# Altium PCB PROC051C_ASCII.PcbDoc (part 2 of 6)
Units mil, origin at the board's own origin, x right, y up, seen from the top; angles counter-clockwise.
Board outline 3304.03 x 2647.77 mil, 6 copper layers (TOP, L2, L3, L4, L5, BOTTOM), stack 55.54 mil thick; 370 components, 273 nets, 1273 pads, 1381 vias.
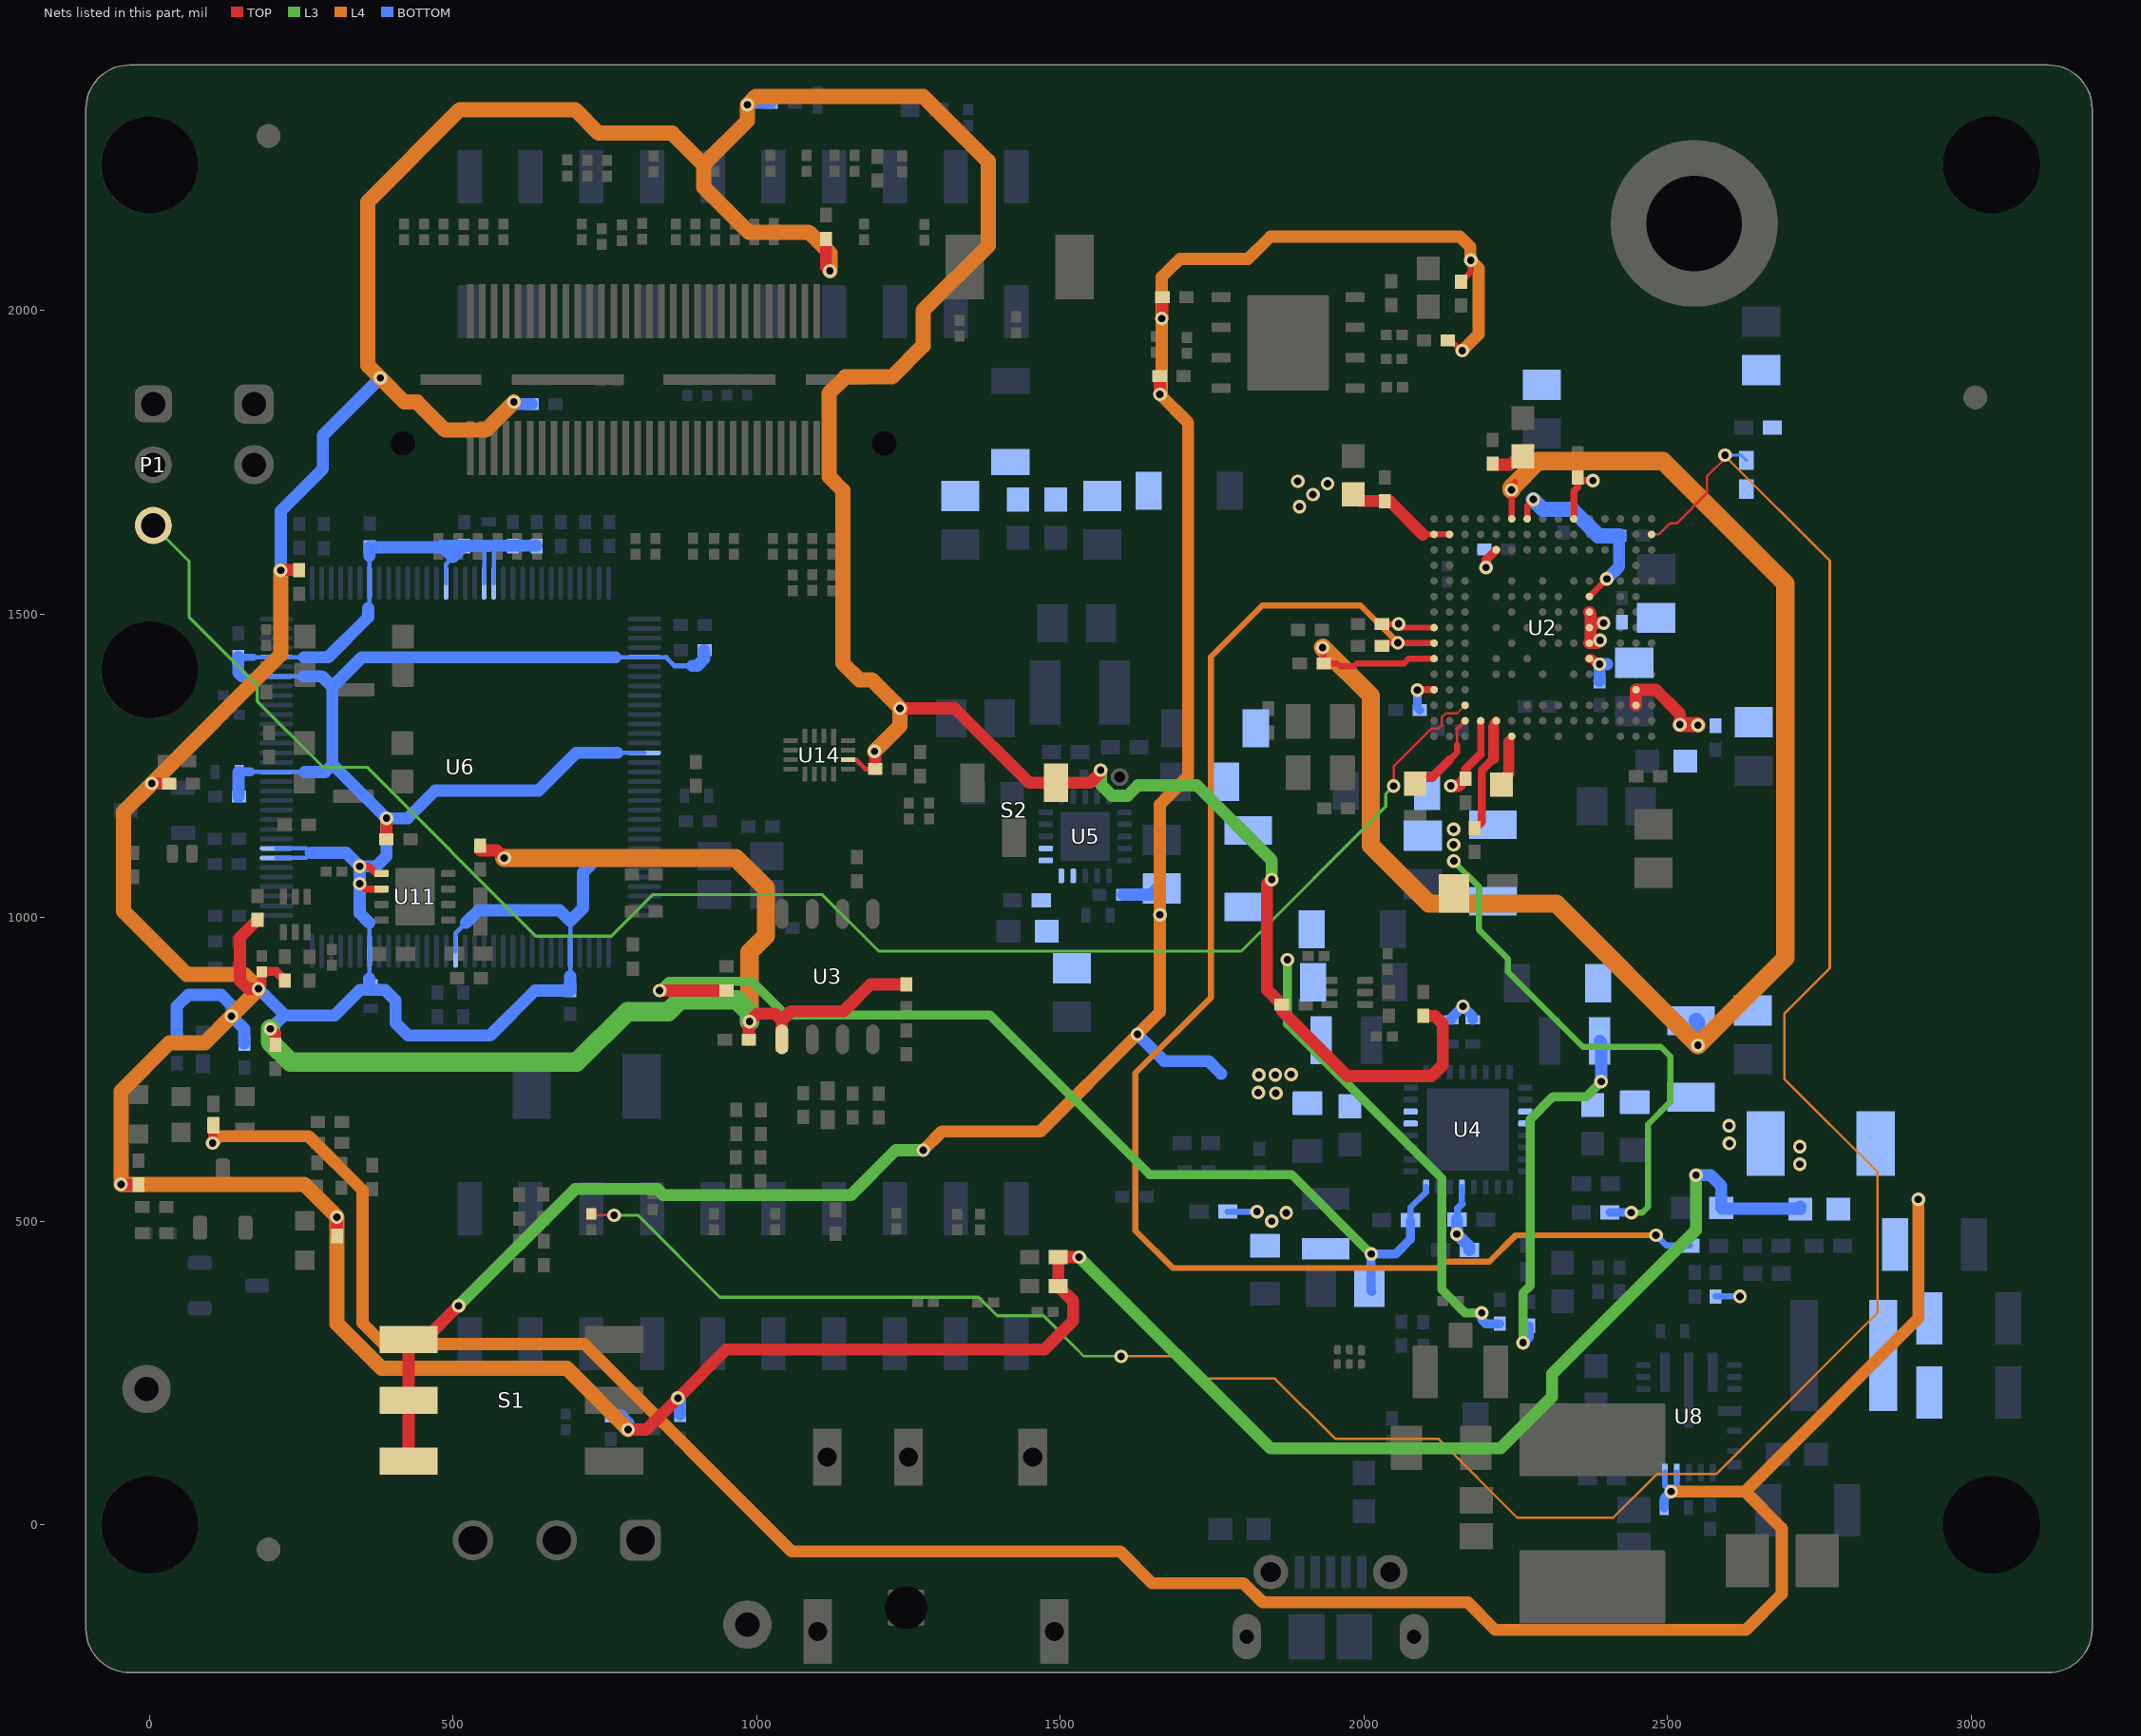
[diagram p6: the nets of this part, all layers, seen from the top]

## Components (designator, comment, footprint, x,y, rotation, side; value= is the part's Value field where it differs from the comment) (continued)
ZZ4 "These assemblies must comply with workmanship standards IPC-A-610 Class 2, unless otherwise specified." AssemblyNote -116.32,3327.82 r0 top
ZZ5 "Micro USB cable, Brackets, Screws, Nuts, Jumpers and Bump on need to be placed in a plastic bag" AssemblyNote -115.53,3255.05 r0 top

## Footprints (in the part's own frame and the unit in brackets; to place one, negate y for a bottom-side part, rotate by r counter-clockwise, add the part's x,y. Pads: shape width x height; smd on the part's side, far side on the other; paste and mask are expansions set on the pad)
0201 [mm] "Data from Kemet datasheet CC101_COM dated 7/28/11"
  rect 0.46x0.42 smd mask+0: 1(-0.33,0) 2(0.33,0)
0201_033 [mm] "SMD, 2-Leads, Height 0.33mm"
  rect 0.46x0.42 smd mask+0: 1(-0.33,0) 2(0.33,0)
0201_Silk [mm] "Data from Kemet datasheet CC101_COM dated 7/28/11"
  rect 0.46x0.42 smd mask+0: 1(-0.33,0) 2(0.33,0)
  silkscreen extent -0.75,-0.4 0.75,0.4
0402 [mm] "0402 from SM-752 data"
  rect 0.8x0.6 smd: 1(-0.6,0) 2(0.6,0)
  silkscreen extent -1.22,-0.52 1.22,0.52
0402_065L [mm] "0402"
  rect 0.6x0.5 smd: 1(-0.5,0) 2(0.5,0)
0402_070 [mil] "SMD, 2-Leads, Body 1.2x0.7mm, Height 0.7mm"
  rect 15x24 smd: 1(-20,0) 2(20,0)
0402L [mm] "0402 from SM-752 data"
  rect 0.6x0.5 smd: 1(-0.5,0) 2(0.5,0)
0402S [mil] "Based on C0402S footprint from PADS legacy"
  rect 15x24 smd: 1(-20,0) 2(20,0)
0603 [mm] "0603 from SM-752 data"
  rect 1x0.95 smd: 1(-0.8,0) 2(0.8,0)
  silkscreen extent -1.52,-0.69 1.52,0.69
0805_HV [mil] "0805 with 30mil clearance between pads"
  rect 50x63 smd: 1(-40,0) 2(40,0)
  silkscreen extent -74,-40 74,40
0805_HV1 [mm] "Custom footprint based on analyzing multiple manufacturer recommendations"
  rrect10% 1x1.25 smd: 1(-1,0) 2(1,0)
  silkscreen extent -0.2,-0.75 0.2,0.75
0805L [mm] "0805 from SM-752 data"
  rect 1.1x1.4 smd: 1(-0.75,0) 2(0.75,0)
1206 [mm] "1206 from SM-752 data"
  rect 1.3x1.85 smd: 1(-1.45,0) 2(1.45,0)
  silkscreen extent -2.4,-1.21 2.4,1.21
1206_180 [mm] "1206_180"
  rect 1.1x1.6 smd: 1(-1.7,0) 2(1.7,0)
  silkscreen extent -0.9,-1 0.9,1
1210_270 [mm] "1210"
  rect 1.3x2.7 smd: 1(-1.45,0) 2(1.45,0)
  silkscreen extent -2.32,-1.57 2.32,1.57
1210_280 [mm] "SMD, 2-Leads, Body 3.6x2.8mm, Height 2.8mm"
  rect 1.1x2.2 smd: 1(-1.65,0) 2(1.65,0)
  silkscreen extent -0.84,-1.4 0.84,1.4
2010 [mm] "Chip Capacitor, Body 5.08x2.54mm, IPC Medium Density"
  rect 1.6x2.7 smd: 1(-2.3,0) 2(2.3,0)
  silkscreen extent -3.42,-1.65 3.42,1.65
2220_345 [mm] "Wurth recommended land pattern"
  rrect3% 3.05x6.1 smd: 1(-3.075,0) 2(3.075,0)
  silkscreen extent -1.3,-3 1.3,3
3528-21 [mm] "Medium Density IPC, based on Kemet datasheet 2016-10-20"
  rrect6% 1.8x2.23 smd: 1(-1.46,0) 2(1.46,0)
  silkscreen extent -2.29,-1.5 0.76,1.5
ABL0161B [mm] "BGA, 161-Balls, Body 10.4x10.4mm, Pitch 0.65mm"
  round 0.32 smd: A1(-4.55,4.55) A2(-3.9,4.55) A3(-3.25,4.55) A5(-1.95,4.55) A7(-0.65,4.55) A9(0.65,4.55) A10(1.3,4.55) A13(3.25,4.55) A14(3.9,4.55) A15(4.55,4.55) B1(-4.55,3.9) B2(-3.9,3.9) B3(-3.25,3.9) B4(-2.6,3.9) B5(-1.95,3.9) B6(-1.3,3.9) B7(-0.65,3.9) B8(0,3.9) B9(0.65,3.9) B10(1.3,3.9) B11(1.95,3.9) B12(2.6,3.9) B13(3.25,3.9) B14(3.9,3.9) B15(4.55,3.9) C1(-4.55,3.25) C2(-3.9,3.25) C3(-3.25,3.25) C4(-2.6,3.25) C5(-1.95,3.25) C6(-1.3,3.25) C7(-0.65,3.25) C8(0,3.25) C9(0.65,3.25) C13(3.25,3.25) C14(3.9,3.25) C15(4.55,3.25) D2(-3.9,2.6) D13(3.25,2.6) D14(3.9,2.6) D15(4.55,2.6) E1(-4.55,1.95) E2(-3.9,1.95) E3(-3.25,1.95) E5(-1.95,1.95) E6(-1.3,1.95) E8(0,1.95) E10(1.3,1.95) E11(1.95,1.95) E13(3.25,1.95) E14(3.9,1.95) E15(4.55,1.95) F2(-3.9,1.3) F3(-3.25,1.3) F5(-1.95,1.3) F9(0.65,1.3) F11(1.95,1.3) F13(3.25,1.3) F14(3.9,1.3) F15(4.55,1.3) G1(-4.55,0.65) G2(-3.9,0.65) G3(-3.25,0.65) G5(-1.95,0.65) G6(-1.3,0.65) G7(-0.65,0.65) G8(0,0.65) G10(1.3,0.65) G13(3.25,0.65) G14(3.9,0.65) G15(4.55,0.65) H2(-3.9,0) H3(-3.25,0) H5(-1.95,0) H7(-0.65,0) H9(0.65,0) H11(1.95,0) H13(3.25,0) H14(3.9,0) H15(4.55,0) J1(-4.55,-0.65) J2(-3.9,-0.65) J3(-3.25,-0.65) J5(-1.95,-0.65) J6(-1.3,-0.65) J7(-0.65,-0.65) J8(0,-0.65) J10(1.3,-0.65) J13(3.25,-0.65) J14(3.9,-0.65) J15(4.55,-0.65) K2(-3.9,-1.3) K3(-3.25,-1.3) K5(-1.95,-1.3) K7(-0.65,-1.3) K8(0,-1.3) K9(0.65,-1.3) K10(1.3,-1.3) K11(1.95,-1.3) K13(3.25,-1.3) K14(3.9,-1.3) K15(4.55,-1.3) L1(-4.55,-1.95) L2(-3.9,-1.95) L3(-3.25,-1.95) L5(-1.95,-1.95) L6(-1.3,-1.95) L8(0,-1.95) L10(1.3,-1.95) L13(3.25,-1.95) L14(3.9,-1.95) L15(4.55,-1.95) M2(-3.9,-2.6) M3(-3.25,-2.6) M14(3.9,-2.6) M15(4.55,-2.6) N1(-4.55,-3.25) N2(-3.9,-3.25) N3(-3.25,-3.25) N4(-2.6,-3.25) N5(-1.95,-3.25) N6(-1.3,-3.25) N7(-0.65,-3.25) N8(0,-3.25) N9(0.65,-3.25) N10(1.3,-3.25) N11(1.95,-3.25) N12(2.6,-3.25) N13(3.25,-3.25) N14(3.9,-3.25) N15(4.55,-3.25) P1(-4.55,-3.9) P2(-3.9,-3.9) P3(-3.25,-3.9) P4(-2.6,-3.9) P5(-1.95,-3.9) P6(-1.3,-3.9) P7(-0.65,-3.9) P8(0,-3.9) P9(0.65,-3.9) P10(1.3,-3.9) P11(1.95,-3.9) P12(2.6,-3.9) P13(3.25,-3.9) P14(3.9,-3.9) P15(4.55,-3.9) R1(-4.55,-4.55) R2(-3.9,-4.55) R3(-3.25,-4.55) R4(-2.6,-4.55) R5(-1.95,-4.55) R6(-1.3,-4.55) R7(-0.65,-4.55) R8(0,-4.55) R9(0.65,-4.55) R10(1.3,-4.55) R11(1.95,-4.55) R12(2.6,-4.55) R13(3.25,-4.55) R14(3.9,-4.55) R15(4.55,-4.55)
  silkscreen extent -5.3,-5.3 5.3,5.3
APHHS1005_Green [mm] "SMD, 2-Leads, Body 1x0.5mm"
  rrect20% 0.7x0.5 smd: 1(-0.45,0) 2(0.45,0)
  silkscreen extent -0.8,-0.65 1.2,0.65
AssemblyNote [mil] "Assembly Note"
AssemblyNoteLabel [mil] "Assembly Note for PCB Labels"
CE_Mark_5mm [mil] "Minimum text height for CE Mark"
CONN_105017-0001 [mm] "Molex Micro USB-B"
  rect 0.4x1.35 smd: 1(-1.3,1.35) 2(-0.65,1.35) 3(0,1.35) 4(0.65,1.35) 5(1.3,1.35)
  oval 1.2x1.9 hole 0.6 slot 1.3 at 90 deg: 6(-3.5,-1.35) 9(3.5,-1.35)
  rect 1.5x1.9 smd: 7(-1,-1.35) 8(1,-1.35)
  round 1.45 hole 0.85: 10(2.5,1.35) 11(-2.5,1.35)
  TOP region: -3.5,-0.4 -2.3,-0.4 -2.3,-2.3 -3.5,-2.3
  TOP region: 3.5,-2.3 2.3,-2.3 2.3,-0.4 3.5,-0.4
  silkscreen extent -4.1,-0.2 4.1,1.4
CUI_PJ-051AH [mm] "DC Power Jack, R/A, TH"
  rrect8% 2.4x1.2 hole 0.8 square: 1(-6.3,3.3) 2(-6.3,-5.3) 3(-6.3,-0.1)
  rrect8% 2.7x1.2 hole 0.8 square: 4(1,-6.2) 5(1,3.7)
  rrect7% 1.5x1.5 hole 1.8 square unplated mask+0: MH1(0,0)
D0008A_L [mm] "SOIC, 8-Leads, Body 4.9x3.9mm, Pitch 1.27mm, IPC High Density"
  oval 1.25x0.55 smd: 1(-2.625,1.905) 2(-2.625,0.635) 3(-2.625,-0.635) 4(-2.625,-1.905) 5(2.625,-1.905) 6(2.625,-0.635) 7(2.625,0.635) 8(2.625,1.905)
  silkscreen extent -3.1,-2.5 0.9,2.5
DBZ0003A_N [mm] "SOT23, 3-Leads, Body 2.9x1.3mm, Pitch 0.95mm, Lead Span 2.4mm, IPC Medium Density"
  rrect17% 1x0.6 smd: 1(-1.2,0.95) 2(-1.2,-0.95) 3(1.2,0)
  silkscreen extent 0.2,-1.5 0.7,1.5
DFE252012P [mm] "TOKO, Pad sizes increased as per request"
  rect 0.9x2 smd: 1(-1.05,0) 2(1.05,0)
  silkscreen extent -0.3,-1.2 0.3,1.2
DRB0008B [mm] "SON, 8-Leads, Body 3x3mm, Pitch 0.65mm, Thermal Pad 2.4x1.65mm, TI Recommended"
  rrect33% 0.6x0.3 smd: 1(-1.4,0.975) 2(-1.4,0.325) 3(-1.4,-0.325) 4(-1.4,-0.975) 5(1.4,-0.975) 6(1.4,-0.325) 7(1.4,0.325) 8(1.4,0.975)
  rrect9% 1.47x1.06 on Top Paste: 9(0,-0.63) 9(0,0.63)
  rrect6% 1.65x2.4 smd paste-1.2: 9(0,0)
  silkscreen extent -1.73,-1.73 1.73,1.73
DRL0006A [mm] "SOTFL, 6-Flat Leads, Body 1.2x1.6x0.6mm, Pitch 0.5mm, TI recommended"
  rrect33% 0.67x0.3 smd: 1(-0.74,0.5) 2(-0.74,0) 3(-0.74,-0.5) 4(0.74,-0.5) 5(0.74,0) 6(0.74,0.5)
  silkscreen extent -0.9,-0.95 0.5,0.95
DRY0006A [mm] "USON-6"
  rrect67% 0.45x0.3 smd paste-0.05 mask+0: 1(-0.275,0.5)
  rrect67% 0.4x0.3 smd paste-0.05 mask+0: 2(-0.3,0) 3(-0.3,-0.5) 4(0.3,-0.5) 5(0.3,0) 6(0.3,0.5)
ESD_Overlay_Small [mil]
  silkscreen extent -62,-48 64,61
FCC_disclaimer [mil]
FIDUCIAL10-20 [mm]
  round 1 smd mask+0: 1(0,0)
  TOP keep-out circle w1.178: c0,0 r0.5
IEC_HotSurface_Small [mil]
  silkscreen extent -107,-93 107,92
JOHNSON_128-0711-201 [mm] "UMC Straight Jack Receptacle, 50 Ohm, SMT"
  rrect10% 1x1.05 smd: 1(0,1.525)
  rrect10% 1.05x2.2 smd: 2(-1.475,0) 3(1.475,0)
  silkscreen extent -0.6,-1.3 0.6,-1.3
Keystone5001 [mil] "For Keystone 500x miniature loop terminals"
  round 80 hole 40: 1(0,0)
  silkscreen extent -52,-52 52,52
KYOCERA_CX3225SA [mm] "SMD, 4-Leads, Body 3.2x2.5mm"
  rrect10% 1.05x1.45 smd: 1(-0.925,1.075) 2(-0.925,-1.075) 3(0.925,-1.075) 4(0.925,1.075)
  silkscreen extent -1.78,1.63 -1.65,1.76
Label_650x200 [mil] "Thermal Transfer Label"
  round 1 on Mech13: 0(0,0)
  silkscreen extent -325,-100 325,100
"LS L29K_Red" [mm] "SMD, 2-Leads, Body 1.3x0.8mm"
  rect 0.8x0.8 smd paste-0.4: 1(-0.75,0) 2(0.75,0)
  silkscreen extent -0.1,-0.5 1.45,0.5
NDK_NX3225SA [mm] "NDK"
  rect 1.2x1.4 smd: 1(-0.8,1.1) 2(-0.8,-1.1) 3(0.8,-1.1) 4(0.8,1.1)
NLCV32 [mm] "TDK"
  rect 1.2x2 smd: 1(-1.6,0) 2(1.6,0)
  silkscreen extent -0.9,-1.4 0.9,1.4
ON-SHORE_OSTTE030161 [mm] "Terminal Block, 3.5mm, 3x1, TH"
  rrect50% 1.7x1.7 hole 1.2: 1(-3.5,0)
  round 1.7 hole 1.2: 2(0,0) 3(3.5,0)
  silkscreen extent -5.25,-3.6 5.25,4.05
PDT0128A [mm] "Thin QFP, 128-Leads, Body 14x14mm, Pitch 0.4mm"
  oval 1.4x0.2 smd: 1(-7.7,6.2) 2(-7.7,5.8) 3(-7.7,5.4) 4(-7.7,5) 5(-7.7,4.6) 6(-7.7,4.2) 7(-7.7,3.8) 8(-7.7,3.4) 9(-7.7,3) 10(-7.7,2.6) 11(-7.7,2.2) 12(-7.7,1.8) 13(-7.7,1.4) 14(-7.7,1) 15(-7.7,0.6) 16(-7.7,0.2) 17(-7.7,-0.2) 18(-7.7,-0.6) 19(-7.7,-1) 20(-7.7,-1.4) 21(-7.7,-1.8) 22(-7.7,-2.2) 23(-7.7,-2.6) 24(-7.7,-3) 25(-7.7,-3.4) 26(-7.7,-3.8) 27(-7.7,-4.2) 28(-7.7,-4.6) 29(-7.7,-5) 30(-7.7,-5.4) 31(-7.7,-5.8) 32(-7.7,-6.2) 65(7.7,-6.2) 66(7.7,-5.8) 67(7.7,-5.4) 68(7.7,-5) 69(7.7,-4.6) 70(7.7,-4.2) 71(7.7,-3.8) 72(7.7,-3.4) 73(7.7,-3) 74(7.7,-2.6) 75(7.7,-2.2) 76(7.7,-1.8) 77(7.7,-1.4) 78(7.7,-1) 79(7.7,-0.6) 80(7.7,-0.2) 81(7.7,0.2) 82(7.7,0.6) 83(7.7,1) 84(7.7,1.4) 85(7.7,1.8) 86(7.7,2.2) 87(7.7,2.6) 88(7.7,3) 89(7.7,3.4) 90(7.7,3.8) 91(7.7,4.2) 92(7.7,4.6) 93(7.7,5) 94(7.7,5.4) 95(7.7,5.8) 96(7.7,6.2)
  oval 0.2x1.4 smd: 33(-6.2,-7.7) 34(-5.8,-7.7) 35(-5.4,-7.7) 36(-5,-7.7) 37(-4.6,-7.7) 38(-4.2,-7.7) 39(-3.8,-7.7) 40(-3.4,-7.7) 41(-3,-7.7) 42(-2.6,-7.7) 43(-2.2,-7.7) 44(-1.8,-7.7) 45(-1.4,-7.7) 46(-1,-7.7) 47(-0.6,-7.7) 48(-0.2,-7.7) 49(0.2,-7.7) 50(0.6,-7.7) 51(1,-7.7) 52(1.4,-7.7) 53(1.8,-7.7) 54(2.2,-7.7) 55(2.6,-7.7) 56(3,-7.7) 57(3.4,-7.7) 58(3.8,-7.7) 59(4.2,-7.7) 60(4.6,-7.7) 61(5,-7.7) 62(5.4,-7.7) 63(5.8,-7.7) 64(6.2,-7.7) 97(6.2,7.7) 98(5.8,7.7) 99(5.4,7.7) 100(5,7.7) 101(4.6,7.7) 102(4.2,7.7) 103(3.8,7.7) 104(3.4,7.7) 105(3,7.7) 106(2.6,7.7) 107(2.2,7.7) 108(1.8,7.7) 109(1.4,7.7) 110(1,7.7) 111(0.6,7.7) 112(0.2,7.7) 113(-0.2,7.7) 114(-0.6,7.7) 115(-1,7.7) 116(-1.4,7.7) 117(-1.8,7.7) 118(-2.2,7.7) 119(-2.6,7.7) 120(-3,7.7) 121(-3.4,7.7) 122(-3.8,7.7) 123(-4.2,7.7) 124(-4.6,7.7) 125(-5,7.7) 126(-5.4,7.7) 127(-5.8,7.7) 128(-6.2,7.7)
  silkscreen extent -7.7,-6.3 6.3,6.99
RGR0020A [mm] "QFN, 20-Leads, Body 3.5x3.5mm, Pitch 0.5mm, Thermal Pad 2.05x2.05mm, TI Recommended"
  rrect42% 0.6x0.24 smd: 1(-1.65,1) 2(-1.65,0.5) 3(-1.65,0) 4(-1.65,-0.5) 5(-1.65,-1) 11(1.65,-1) 12(1.65,-0.5) 13(1.65,0) 14(1.65,0.5) 15(1.65,1)
  rrect42% 0.24x0.6 smd: 6(-1,-1.65) 7(-0.5,-1.65) 8(0,-1.65) 9(0.5,-1.65) 10(1,-1.65) 16(1,1.65) 17(0.5,1.65) 18(0,1.65) 19(-0.5,1.65) 20(-1,1.65)
  rrect5% 2.05x2.05 smd paste-1.025: 21(0,0)
  silkscreen extent -1.97,-1.97 1.97,1.97
RHB0032N [mm] "QFN, 32-Leads, Body 5x5mm, Pitch 0.5mm, Thermal Pad 3.45x3.45mm"
  rrect40% 0.6x0.25 smd: 1(-2.4,1.75) 2(-2.4,1.25) 3(-2.4,0.75) 4(-2.4,0.25) 5(-2.4,-0.25) 6(-2.4,-0.75) 7(-2.4,-1.25) 8(-2.4,-1.75) 17(2.4,-1.75) 18(2.4,-1.25) 19(2.4,-0.75) 20(2.4,-0.25) 21(2.4,0.25) 22(2.4,0.75) 23(2.4,1.25) 24(2.4,1.75)
  rrect40% 0.25x0.6 smd: 9(-1.75,-2.4) 10(-1.25,-2.4) 11(-0.75,-2.4) 12(-0.25,-2.4) 13(0.25,-2.4) 14(0.75,-2.4) 15(1.25,-2.4) 16(1.75,-2.4) 25(1.75,2.4) 26(1.25,2.4) 27(0.75,2.4) 28(0.25,2.4) 29(-0.25,2.4) 30(-0.75,2.4) 31(-1.25,2.4) 32(-1.75,2.4)
  rrect3% 3.45x3.45 smd paste-1.725: 33(0,0)
  rrect7% 1.49x1.49 on Bottom Paste: ""(-0.845,-0.845) ""(-0.845,0.845) ""(0.845,-0.845) ""(0.845,0.845)
  silkscreen extent -2.72,-2.73 2.72,2.73
RNL0022A_NV [mm] "VQFN-HR-22"
  rrect25% 0.6x0.4 smd: 1(-1.9,2) 17(1.9,2)
  rrect40% 0.6x0.25 smd: 2(-1.9,1.425) 3(-1.9,0.575) 5(-1.9,-1.175) 6(-1.9,-1.675) 7(-1.9,-2.175) 11(1.9,-2.175) 12(1.9,-1.675) 13(1.9,-1.175) 15(1.9,0.575) 16(1.9,1.425)
  rrect25% 1x0.4 smd paste-0.25: 4(-1.7,-0.25) 14(1.7,-0.25)
  rrect25% 0.4x0.4 on Bottom Paste: 4A(-2,-0.25) 4B(-1.4,-0.25) 14A(1.4,-0.25) 14B(2,-0.25)
  rrect25% 0.4x1.65 smd paste-0.25: 8(-1,-1.875) 10(1,-1.875)
  rrect25% 0.4x0.66 on Bottom Paste: 8A(-1,-1.445) 8B(-1,-2.305) 10A(1,-1.445) 10B(1,-2.305)
  rrect25% 0.4x3.15 smd paste-0.25: 9(0,-1.125)
  rrect25% 0.4x0.63 on Bottom Paste: 9A(0,0.12) 9B(0,-0.71) 9C(0,-1.54) 9D(0,-2.37)
  rrect40% 0.25x0.75 smd: 18(1,2.325) 19(0.5,2.325) 20(0,2.325) 21(-0.5,2.325) 22(-1,2.325)
RSV0016A [mm] "QFN, 16-Leads, Body 1.8x2.6mm, Pitch 0.4mm, TI Recommended"
  rect 0.7x0.2 smd: 1(-0.75,0.6)
  rect 0.6x0.2 smd: 2(-0.8,0.2) 3(-0.8,-0.2) 4(-0.8,-0.6) 9(0.8,-0.6) 10(0.8,-0.2) 11(0.8,0.2) 12(0.8,0.6)
  rect 0.2x0.6 smd: 5(-0.6,-1.2) 6(-0.2,-1.2) 7(0.2,-1.2) 8(0.6,-1.2) 13(0.6,1.2) 14(0.2,1.2) 15(-0.2,1.2) 16(-0.6,1.2)
  silkscreen extent -1.08,-1.33 1.08,1.45
SAMTEC_QSH-030-01-X-D-A [mm] "Receptacle, 0.5 mm, 30x2, TH"
  rect 2.27x0.279 smd: 1(-2.865,7.25) 2(2.865,7.25) 3(-2.865,6.75) 4(2.865,6.75) 5(-2.865,6.25) 6(2.865,6.25) 7(-2.865,5.75) 8(2.865,5.75) 9(-2.865,5.25) 10(2.865,5.25) 11(-2.865,4.75) 12(2.865,4.75) 13(-2.865,4.25) 14(2.865,4.25) 15(-2.865,3.75) 16(2.865,3.75) 17(-2.865,3.25) 18(2.865,3.25) 19(-2.865,2.75) 20(2.865,2.75) 21(-2.865,2.25) 22(2.865,2.25) 23(-2.865,1.75) 24(2.865,1.75) 25(-2.865,1.25) 26(2.865,1.25) 27(-2.865,0.75) 28(2.865,0.75) 29(-2.865,0.25) 30(2.865,0.25) 31(-2.865,-0.25) 32(2.865,-0.25) 33(-2.865,-0.75) 34(2.865,-0.75) 35(-2.865,-1.25) 36(2.865,-1.25) 37(-2.865,-1.75) 38(2.865,-1.75) 39(-2.865,-2.25) 40(2.865,-2.25) 41(-2.865,-2.75) 42(2.865,-2.75) 43(-2.865,-3.25) 44(2.865,-3.25) 45(-2.865,-3.75) 46(2.865,-3.75) 47(-2.865,-4.25) 48(2.865,-4.25) 49(-2.865,-4.75) 50(2.865,-4.75) 51(-2.865,-5.25) 52(2.865,-5.25) 53(-2.865,-5.75) 54(2.865,-5.75) 55(-2.865,-6.25) 56(2.865,-6.25) 57(-2.865,-6.75) 58(2.865,-6.75) 59(-2.865,-7.25) 60(2.865,-7.25)
  round 0 hole 1.02 unplated mask+0: MH1(2.67,10.065) MH2(2.67,-10.065)
  rect 0.43x2.54 smd: MP1(0,8.065) MP4(0,-8.065)
  rect 0.43x4.7 smd: MP2(0,3.175) MP3(0,-3.175)
  silkscreen extent -3.9,-10.66 3.62,10.66
SAMTEC_SSM-110-X-DV [mm] "Receptacle, 2.54mm, 10x2, SMT"
  rrect10% 1.02x2.22 smd: 1(-11.43,2.825) 2(-11.43,-2.825) 3(-8.89,2.825) 4(-8.89,-2.825) 5(-6.35,2.825) 6(-6.35,-2.825) 7(-3.81,2.825) 8(-3.81,-2.825) 9(-1.27,2.825) 10(-1.27,-2.825) 11(1.27,2.825) 12(1.27,-2.825) 13(3.81,2.825) 14(3.81,-2.825) 15(6.35,2.825) 16(6.35,-2.825) 17(8.89,2.825) 18(8.89,-2.825) 19(11.43,2.825) 20(11.43,-2.825)
  silkscreen extent -13.02,-2.54 12.7,2.54
Samtec_TSW-103-07-T-S [mm] "Header, 2.54 mm, 3x1, TH"
  rrect50% 1.55x1.55 hole 1.02: 1(-2.54,0)
  round 1.55 hole 1.02: 2(0,0) 3(2.54,0)
SML-E1_Yellow [mm] "SMD, 2-Leads, Body 1.6x0.8mm"
  rect 0.8x0.8 smd: 1(0.825,0) 2(-0.825,0)
  silkscreen extent -1.8,-0.8 1.3,0.8
SOD-882 [mm] "Skyworks"
  rrect42% 0.475x0.75 smd mask+0: 1(-0.412,0) 2(0.412,0)
  rrect42% 0.475x0.75 on Top Solder mask+0: 1(-0.412,0) 2(0.412,0)
  silkscreen extent -1.1,-0.35 -0.87,0.35
SOT-23 [mm] "SOT23, 3-Leads, Body 2.9x1.3mm, Pitch 0.95mm, Lead Span 2.5mm, IPC Medium Density"
  rrect50% 1x0.6 smd: 1(-1.2,0.95) 2(-1.2,-0.95) 3(1.2,0)
  silkscreen extent -1.62,-1.5 0.7,1.5
SW_219-3MST [mm] "SMD, 6-Leads, Body 6.7x9.09mm, Pitch 2.54mm"
  rect 2.44x1.13 smd: 1(-4.3,2.54) 2(-4.3,0) 3(-4.3,-2.54) 4(4.3,-2.54) 5(4.3,0) 6(4.3,2.54)
  silkscreen extent -3.35,-4.54 3.35,4.54
SW_CJS_1201A [mm] "Copal- Electronics"
  rect 1x1.6 smd paste+0 mask+0: 1(-1.75,-1.15) 2(0,1.15) 3(1.75,-1.15)
  silkscreen extent -3,-1.6 -2.7,-0.8
SW_KMR243GLFG [mm] "SMD, 5-Leads, Body 4.2x2.8mm"
  rrect11% 0.9x1 smd: 1(-2.05,0.8) 2(2.05,0.8) 3(-2.05,-0.8) 4(2.05,-0.8)
  rrect18% 1.7x0.55 smd: 5(0,1.425)
  silkscreen extent -3.1,0.7 -2.9,0.9
TI_STACKED_OVERLAY_SMALL [mil]
TP_H045P075 [mm] "TP_H0.45P0.75"
  round 0.75 hole 0.45: 1(0,0)
TSW-102-07-G-S [mm] "Samtec 100mil, 1x2, 230 mil above insulator"
  rrect50% 1.65x1.65 hole 1.016: 1(-1.27,0)
  round 1.65 hole 1.016: 2(1.27,0)
WEEE_Minimum [mil] "WEEElie bin"
  silkscreen extent 22,-71 54,74
WSON-8L_6x5MM_EP [mm] "SMD, 8-Leads, Body 6x5mm, Pitch 1.27mm"
  rrect25% 0.8x0.4 smd: 1(-2.8,1.905) 2(-2.8,0.635) 3(-2.8,-0.635) 4(-2.8,-1.905) 5(2.8,-1.905) 6(2.8,-0.635) 7(2.8,0.635) 8(2.8,1.905)
  rrect3% 3.4x4 smd paste-3: 9(0,0)
  rrect7% 1.468x1.698 on Top Paste: ""(-0.834,-0.949) ""(-0.834,0.949) ""(0.834,-0.949) ""(0.834,0.949)
  silkscreen extent -3.2,-2.7 3.2,2.7
XAL5030 [mil] "Coilcraft XAL5030 12/12/11"
  rect 46x183 smd: 1(-65,0) 2(65,0)
  silkscreen extent -108,-112 108,112

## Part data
C1 C13 C14 C33 C36 C54 C94: library part CMP-0007136-5, "CAP, CERM, 1 uF, 16 V, +/- 10%, X7R, AEC-Q200 Grade 1, 0603"
C2: library part CMP-0006325-2, "CAP, CERM, 0.1 uF, 50 V, +/- 10%, X7R, AEC-Q200 Grade 1, 0402"
C3 C5 C7 C10 C12 C39 C47 C48 C51 C53 C56 C57 C84 C90: library part CMP-0078265-1, "CAP, CERM, 0.22 µF, 16 V,+/- 10%, X7R, AEC-Q200 Grade 1, 0402"
C4 C6 C11 C22: library part CMP-0006351-2, "CAP, CERM, 0.1 uF, 16 V, +/- 10%, X7R, 0402"
C8: library part CMP-0064969-1, "CAP, CERM, 0.1 uF, 10 V,+/- 10%, X7S, 0201"
C9 C15: library part CMP-0006367-2, "CAP, CERM, 4.7 pF, 50 V, +/- 2%, C0G/NP0, 0402"
C16 C20 C42 C43 C49 C64 C67 C71 C75 C91 C92 C97: library part CMP-0078241-1, "CAP, CERM, 0.1 µF, 10 V,+/- 10%, X7R, 0402"
C17 C40 C45 C52 C55 C58 C59 C65 C80 C83 C95 C96 C98 C100 C102 C103 C104: library part CMP-0008017-2, "CAP, CERM, 10 uF, 10 V, +/- 10%, X7R, 0805"
C18: library part CMP-0006717-2, "CAP, CERM, 0.47 uF, 6.3 V, +/- 10%, X7R, 0402"
C19 C37 C99 C105: library part CMP-0008770-2, "CAP, CERM, 22 uF, 6.3 V, +/- 10%, X7R, AEC-Q200 Grade 1, 1206"
C21 C25: library part CMP-0009155-2, "CAP, CERM, 10 uF, 25 V, +/- 20%, X7R, AEC-Q200 Grade 1, 1210"
C23 C27: library part CMP-0085252-1, "CAP, CERM, 0.047 µF, 50 V,+/- 5%, X7R, 0603"
C24: library part CMP-0006361-2, "CAP, CERM, 4700 pF, 50 V, +/- 10%, X7R, AEC-Q200 Grade 1, 0402"
C26: library part CMP-0078216-1, "CAP, TA, 47 µF, 10 V, +/- 10%, SMD"
C28 C34 C77 C78 C82: library part CMP-0006201-2, "CAP, CERM, 0.1 uF, 16 V, +/- 10%, X7R, 0402"
C29 C30 C31: library part CMP-0009174-2, "CAP, CERM, 22 uF, 16 V, +/- 10%, X7R, 1210"
C32 C79: library part CMP-0076706-1, "CAP, CERM, 4.7 µF, 25 V,+/- 10%, X7R, AEC-Q200 Grade 1, 0805"
C35 C46 C81: library part CMP-0007995-2, "CAP, CERM, 10 uF, 16 V, +/- 10%, X7R, 0805"
C38 C60 C68: library part CMP-0008809-2, "CAP, CERM, 22 uF, 6.3 V, +/- 10%, X7R, AEC-Q200 Grade 1, 1206"
C41 C61 C62 C76: library part CMP-0006349-2, "CAP, CERM, 1 uF, 10 V, +/- 10%, X7S, AEC-Q200 Grade 1, 0402"
C44: library part CMP-0009172-2, "CAP, CERM, 47 uF, 6.3 V, +/- 10%, X7R, AEC-Q200 Grade 1, 1210"
C50 C66 C69: library part CMP-0078218-1, "CAP, CERM, 0.01 µF, 16 V,+/- 10%, X7R, 0402"
C63 C70: library part CMP-0087060-3, "Cap Ceramic 8pF 50V C0G 0.5pF SMD 0402 125C Paper T/R"
C72 C73 C101: library part CMP-0006352-2, "CAP, CERM, 0.01 uF, 25 V, +/- 10%, X7R, 0402"
C74 C86: library part CMP-0006302-2, "CAP, CERM, 2.2 uF, 10 V, +/- 10%, X7S, 0402"
C85: library part CMP-0006624-2, "CAP, CERM, 1 uF, 6.3 V, +/- 20%, X7R, 0402"
C87 C89: library part CMP-0007134-5, "CAP, CERM, 2.2 uF, 6.3 V, +/- 10%, X7R, AEC-Q200 Grade 1, 0603"
C88: library part CMP-0006242-2, "CAP, CERM, 33 pF, 50 V, +/- 5%, C0G/NP0, 0402"
C93: library part CMP-0084680-1, "CAP, CERM, 22 µF, 25 V,+/- 20%, X5R, AEC-Q200 Grade 3, 0805"
"CAUTION HOT SURFACE": library part CMP-0074837-1, "IEC 61010-1 Hot Surface Warning"
D2: library part CMP-0078187-2, "Diode, Schottky,  V, 0.01 A, SOD-882"
D5: library part CMP-0067682-2, "LED, Green, SMD"
DS1 DS2: library part CMP-0002902-2, "LED, Red, SMD"
DS3 DS4: library part CMP-0002977-3, "LED, Yellow, SMD"
"ESD Susceptible": library part CMP-0074840-1, "ESD Susceptible Symbol"
F1: library part CMP-0003458-2, "Fuse, 5 A, 32VAC/VDC, SMD"
FID1 FID2 FID3 FID4 FID5 FID6: library part CMP-0077181-1, "Fiducial mark.  There is nothing to buy or mount."
J1: library part CMP-0075524-1, "Receptacle, 0.5 mm, 30x2, Gold, TH"
J2: library part CMP-0055788-1, "UMC Straight Jack Receptacle, 50 Ohm, Gold, SMT"
J3: library part CMP-0075352-1, "Terminal Block, 3.5mm, 3x1, Tin, R/A, TH"
J5 J6: library part CMP-0078182-1, "Receptacle, 2.54mm, 10x2, Gold with Tin tail, SMT"
J8: library part CMP-0055293-1, "Connector, Receptacle, Micro-USB Type B, R/A, Bottom Mount SMT"
L1: library part CMP-0061001-2, "Inductor, Shielded, Composite, 2.2 µH, 9.2 A, 0.01 ohm, AEC-Q200 Grade 1, SMD"
L2 L3: library part CMP-0058944-1, "Inductor, Shielded, 470 nH, 4.7 A, 0.021 ohm, SMD"
L4: library part CMP-0058938-1, "Inductor, Shielded, 1 uH, 3.8 A, 0.035 ohm, AEC-Q200 Grade 1, SMD"
L5 L6 L10: library part CMP-0083745-1, "Inductor, Wirewound, Ferrite, 100 nH, 2.85 A, 0.024 ohm, AEC-Q200 Grade 1, SMD"
L7: library part CMP-0003388-1, "Ferrite Bead, 600 ohm @ 100 MHz, 4 A, 2220"
L8 L9: library part CMP-0077879-2, "Ferrite Bead, 120 ohm @ 100 MHz, 1.9 A, 0603"
LBL1: library part CMP-0003625-1, "Thermal Transfer Printable Labels, 0.650\" W x 0.200\" H - 10,000 per roll"
Logo1: library part CMP-0074838-1, "Texas Instrument Corporate Signature"
Logo2: library part CMP-0074847-1, "FCC_disclaimer"
LOGO3: library part CMP-0074844-1
Logo4: library part CMP-0074769-1
P1: library part CMP-0075530-2, "Header, 2.54 mm, 3x1, Tin, TH"
P6: library part CMP-0081851-1, "DC Power Jack, R/A, TH"
P7: library part CMP-0075405-2, "Header, 100mil, 2x1, Gold, TH"
Q1 Q2: library part CMP-0000947-2, "MOSFET, N-CH, 100 V, 0.17 A, SOT-23"
R1 R2 R4 R5 R6 R7 R8 R9 R10 R17 R18 R19 R20 R21 R22 R23 R24 R25 R26 R27 R28 R29 R30 R31 R32 R33 R35 R36 R48 R49 R50 R51 R52 R53 R58 R59 R60 R62 R63 R64 R65 R66 R67 R69 R70 R71 R72 R75 R76 R94 R102 R104 R105 R106 R108 R109 R111 R135 R136 R162 R163 R164 R165 R166 R167 R168 R169 R198 R199 R201: library part CMP-0027008-4, "RES, 0, 5%, 0.05 W, 0201"
R3 R13 R14 R15 R16 R41 R43 R73 R74 R86 R89 R91 R98 R113 R155 R158 R177 R194 R197 R208: library part CMP-0025958-3, "RES, 10.0 k, 1%, 0.063 W, AEC-Q200 Grade 0, 0402"
R11 R12 R37 R78 R97 R107 R128 R129 R141 R152 R178 R196 R200: library part CMP-0026992-3, "RES, 0, 5%, 0.1 W, AEC-Q200 Grade 0, 0402"
R34 R115 R156: library part CMP-0016044-3, "RES, 0, 5%, 0.75 W, AEC-Q200 Grade 0, 2010"
R38: library part CMP-0026395-2, "RES, 47.5 k, 1%, 0.063 W, AEC-Q200 Grade 0, 0402"
R39 R40 R42 R44 R45: library part CMP-0027275-3, "RES, 33.2, 1%, 0.05 W, 0201"
R46 R47 R81 R100 R119 R120 R121 R143 R144 R147 R148 R149 R157 R159 R188 R189: library part CMP-0026822-3, "RES, 0, 5%, 0.063 W, AEC-Q200 Grade 0, 0402"
R54 R55 R56 R57 R179 R180 R181 R182 R183 R184: library part CMP-0078192-2, "RES, 20.0, 1%, 0.05 W, 0201"
R61: library part CMP-0026658-1, "RES, 10.0 k, 1%, 0.1 W, 0402"
R68 R77 R79 R80 R154: library part CMP-0026993-2, "RES, 100, 5%, 0.1 W, AEC-Q200 Grade 0, 0402"
R82 R142 R186 R190: library part CMP-0026825-5, "RES, 10 k, 5%, 0.063 W, AEC-Q200 Grade 0, 0402"
R83: library part CMP-0025754-4, "RES, 20, 5%, 0.1 W, AEC-Q200 Grade 0, 0603"
R84: library part CMP-0026823-3, "RES, 100 k, 5%, 0.063 W, AEC-Q200 Grade 0, 0402"
R85 R87: library part CMP-0026491-2, "RES, 61.9, 1%, 0.063 W, AEC-Q200 Grade 0, 0402"
R88 R96 R114: library part CMP-0026574-2, "RES, 82.5 k, 1%, 0.063 W, AEC-Q200 Grade 0, 0402"
R90 R103 R117 R202: library part CMP-0078194-1, "RES, 360, 5%, 0.1 W, AEC-Q200 Grade 0, 0402"
R92 R95 R99: library part CMP-0026557-2, "RES, 7.87 k, 1%, 0.063 W, AEC-Q200 Grade 0, 0402"
R93 R101 R112: library part CMP-0026542-2, "RES, 750, 1%, 0.063 W, AEC-Q200 Grade 0, 0402"
R110 R138 R172 R173: library part CMP-0025950-3, "RES, 100 k, 1%, 0.063 W, AEC-Q200 Grade 0, 0402"
R116 R160: library part CMP-0078212-1, "RES, 510, 5%, 0.1 W, AEC-Q200 Grade 0, 0402"
R118: library part CMP-0026878-3, "RES, 220, 5%, 0.063 W, AEC-Q200 Grade 0, 0402"
R122: library part CMP-0083631-1, "RES, 12.1 k, 0.1%, 0.063 W, AEC-Q200 Grade 0, 0402"
R123 R124 R126 R127 R140: library part CMP-0026071-3, "RES, 1.00 k, 1%, 0.063 W, AEC-Q200 Grade 0, 0402"
R125: library part CMP-0026413-2, "RES, 4.87 k, 1%, 0.063 W, AEC-Q200 Grade 0, 0402"
R130 R133 R137 R161 R175: library part CMP-0025884-3, "RES, 0, 5%, 0.125 W, 0603"
R131 R132: library part CMP-0026918-5, "RES, 3.3 k, 5%, 0.063 W, AEC-Q200 Grade 0, 0402"
R134: library part CMP-0026404-2, "RES, 49.9, 1%, 0.063 W, AEC-Q200 Grade 0, 0402"
R139: library part CMP-0026781-1, "RES, 4.87 k, 0.1%, 0.062 W, AEC-Q200 Grade 0, 0402"
R145: library part CMP-0083632-1, "RES, 48.7 k, 0.1%, 0.063 W, AEC-Q200 Grade 0, 0402"
R146: library part CMP-0083657-1, "RES, 4.42 k, 0.1%, 0.063 W, AEC-Q200 Grade 0, 0402"
R150: library part CMP-0025951-3, "RES, 100, 1%, 0.063 W, AEC-Q200 Grade 0, 0402"
R151 R153: library part CMP-0078210-2, "RES, 330 k, 1%, 0.063 W, AEC-Q200 Grade 0, 0402"
R170 R171: library part CMP-0026244-2, "RES, 2.94 k, 1%, 0.063 W, AEC-Q200 Grade 0, 0402"
R174: library part CMP-0078244-2, "RES, 30.0 k, 1%, 0.063 W, AEC-Q200 Grade 0, 0402"
R193: library part CMP-0026207-2, "RES, 26.1 k, 1%, 0.063 W, AEC-Q200 Grade 0, 0402"
S1: library part CMP-0002269-1, "Switch, SPST, Slide, Off-On, 3 Pos, 0.1A, 20V, SMD"
S2: library part CMP-0002159-2, "Slide SW, SPDT 0.1A 50VDC"
SW1 SW2: library part CMP-0002325-1, "Switch, SPST-NO, Off-Mom, 0.01 A, 32 VDC, SMD"
TP1 TP3: library part CMP-0055138-1, "Test Point, Miniature, Black, TH"
TP2: library part CMP-0003719-1, "Testpoint"
U1: library part CMP-0079267-1, "2.3V-3.6V, 16M-BIT [x 1/x 2/x 4] CMOS FLASH Memory, WSON-8"
U2: library part CMP-0078239-1, "AWR1843ABL, ABL0161B (FCBGA-161)"
U3: library part CMP-0075992-1, "Automotive Fault Protected CAN Transceiver With Flexible Data-Rate, D0008A (SOIC-8)"
U4: library part CMP-0078631-1, "Boost and Dual Buck Regulators With Diagnostic Functions, RHB0032N (VQFN-32)"
U5: library part CMP-0077268-2, "Automotive 3A High-Accuracy Low-Noise Low-Dropout (LDO) Voltage Regulator, RGR0020A (VQFN-20)"
U6: library part CMP-0029856-2, "Tiva C Series Microcontroller, 1024 KB Flash, 256 KB SRAM, 12 Bit, 20 Channels, -40 to 105 degC, 128-Pin TQFP (PDT), Green (RoHS & no Sb/Br), Tray"
U7: library part CMP-0033001-1, "Precision Micropower Shunt Voltage Reference, 0.5% accuracy, 2.5 V, 15 ppm / degC, 15 mA, -40 to 125 degC, 3-pin SOT-23 (DBZ), Green (RoHS & no Sb/Br)"
U8: library part CMP-0076346-4, "2.5A, 36 V Synchronous, 2.1MHz, Automotive Step Down DC-DC Converter, RNL0022A (VQFN-HR-22)"
U10: library part CMP-0043115-3, "4-Channel ESD Protection Array for High-Speed Data Interfaces, DRY0006A (USON-6)"
U11: library part CMP-0036402-3, "Single Output High PSRR LDO, 1 A, Adjustable 1.2 to 5.5 V Output, 2.7 to 5.5 V Input, 8-pin SON (DRB), -40 to 125 degC, Green (RoHS & no Sb/Br)"
U12 U13: library part CMP-0067397-2, "1.4V-Capable +/-0.5degC Temperature Sensor with Alert Function and I2C/SMBus interface in SOT-563, DRL0006A (SOT-OTHER-6)"
U14: library part CMP-0067415-1, "10-Ohm Quad SPDT Analog Switch, RSV0016A (UQFN-16)"
Y1: library part CMP-0004694-3, "Crystal, 40 MHz, 8pF, SMD"
Y2: library part CMP-0078214-2, "Crystal, 16 MHz, 15 ppm, 8 pF, AEC-Q200 Grade 1, SMD"
ZZ1: library part CMP-0003616-3
ZZ2: library part CMP-0077236-1
ZZ3: library part CMP-0077237-1
ZZ4: library part CMP-0077238-1
ZZ5: library part AssemblyNote

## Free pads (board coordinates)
  round 275.59 hole 157.48: 1(2543.95,2143.55)
  round 160 hole 160 unplated mask+0: ""(0,0) ""(0,1408.1) ""(0,2240) ""(3033.56,0) ""(3033.56,2240)

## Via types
v1: diameter 22.4, hole 12.2, TOP to BOTTOM, tented both sides, 811 vias
v2: diameter 15.74, hole 5.9, TOP to L2, tented both sides, 528 vias
v3: diameter 19.68, hole 7.87, TOP to BOTTOM, 23 vias
v4: diameter 19.68, hole 7.87, TOP to BOTTOM, tented both sides, 7 vias
v5: diameter 22.4, hole 12.1, TOP to BOTTOM, tented both sides, 7 vias
v6: diameter 16, hole 8, TOP to BOTTOM, tented both sides, 4 vias
v7: diameter 15.74, hole 5.9, TOP to L2, tented top, 1 vias

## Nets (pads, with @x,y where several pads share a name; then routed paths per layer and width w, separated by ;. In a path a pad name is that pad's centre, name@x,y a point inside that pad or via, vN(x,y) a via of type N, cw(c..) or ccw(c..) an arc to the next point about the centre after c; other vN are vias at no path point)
1V8: C38.1 L2.2 L6.1 R119.1 | length 616.2
  L3 w15: v1(2262,300) 2262,382 2274,394 2274,668 2311.29,705.29 2366.31,705.29 2390.62,729.6 v1(2390.62,730.13)
  BOTTOM w15: v1(2262,300) 2263,300 2272,309 R119.1@2272,328
  BOTTOM w20: L2.2@2388.34,797 2390.62,794.72 v1(2390.62,730.13)
1V24: C33.2 C34.1 C40.1 C60.1 C68.1 L3.2 L5.1 R121.1 U5.14 U5.15 U5.16 U5.17 | length 774.1
  L3 w15: v1(1874,931) 1874,825 2128.3,570.7 2128.3,387.7 2167,349 v1(2194,349)
  BOTTOM w15: v1(2194,349) 2194,338 2200.68,331.32 R121.1@2224,331.32
3V3: C28.1 C29.1 C30.1 C31.1 D5.1 L1.2 R133.1 R156.1 U8.21 U8.22 | length 4125
  TOP w15: v1(104,629) 104,657.28 D5.1@105,658.28
  L4 w20: v1(104,629) 115.2,640.2 262,640.2 350.93,551.26 350.93,332.07 385,298 716,298 1057.61,-43.61 1598.66,-43.61 1651.36,-96.31 1802.03,-96.31 1833.22,-127.5 2170.81,-127.5 2216.3,-173 2629,-173 2688.36,-113.64 2688.36,-5.63 2627.73,55 ; v1(2506,55) 2627.73,55 ; v1(2913,536) 2913,340.27 2627.73,55
  BOTTOM w10: U8.22@2495.63,86.19 2495.63,65.37 v1(2506,55) 2515.31,64.31 U8.21@2515.31,86.19
  BOTTOM w15: C28.1@2494.45,28.45 2494.45,43.45 v1(2506,55)
3V3_REF: C22.1 C35.1 C36.2 C46.1 C54.2 C59.1 C81.1 L4.1 L10.1 R37.1 R38.2 R41.2 R43.2 R120.1 R131.2 R132.2 R141.1 R142.2 R156.2 R186.2 S1.4 S1.5 S1.6 U4.5 U4.13 U4.14 U4.27 U4.28 | length 4316.4
  TOP w10: R41.2@2138.24,1950.98 2143.02,1950.98 v1@2161,1933 ; R37.1@2160,2047.68 2176,2063.68 v1(2176,2083)
  TOP w20: S1.6@426.71,105 S1.5@426.71,205 S1.4@426.71,305 453,305 v1(509,361) ; R43.2@1663.51,1892 1664,1891.51 v1(1664,1862) ; v1@1668.11,1990.39 R38.2@1668.11,2021.84
  L3 w20: v1(509,361) 701.27,553.27 835.83,553.27 845.9,543.2 1155.2,543.2 1229,617 v1(1274,617)
  L4 w20: v1(1274,617) 1305.05,648.05 1467.05,648.05 v1(1627,808) 1664,845 v1(1664,1005) 1664,1186.47 1710.4,1232.87 1710.4,1693.66 1710.33,1693.73 1710.33,1716.27 1710.4,1716.34 1710.4,1815.6 v1(1664,1862) 1667,1865 v1(1667,1987) 1667,2055.47 1688.73,2077.2 1689.2,2077.2 1697,2085 1809,2085 1846,2122 2158,2122 2175.2,2104.8 2175.2,2083.8 v1(2176,2083) 2189,2070 2189,1961 v1(2162,1934)
  BOTTOM w10: R186.2@1775.62,516 v1(1824,516) ; 2161.43,528.43 U4.5@2161.43,556.78 ; R141.1@2579,376.32 v1(2619.32,376.32)
  BOTTOM w12: C22.1@2153.38,503 2154,503.62 2154,521 2161.43,528.43
  BOTTOM w16: R132.2@2144,832 2144,835 v1(2163,854) 2179,838 R131.2@2179,832
  BOTTOM w20: R120.1@1603.68,1038 1649,1038 1659,1048 1663,1044 1664,1043 v1(1664,1005) ; v1(1627,808) 1671,764 1744,764 1765,743 ; C22.1@2153.38,503 2153.38,479.38 v1(2153,479) 2173.62,458.38 R142.2@2173.62,453
  other v1: 1848,500 1872,514 2718,594 2718,623 2601.93,628.3 2601.45,657.58 1855,711 1826,712 1827,741 1854,741 1880,742
5VBST: C82.1 C93.1 R78.2 U4.8 | length 1709.4
  TOP w20: v1(840,880) R78.2@950.31,880 R78.2@951.1,880
  L3 w15: v1(840,880) 855,895 992.5,895 1047.5,840 1384,840 1647.21,576.79 1881.21,576.79 v1(2012,446)
  BOTTOM w10: C82.1@2076.62,502 2076.62,522.62 2102.37,548.37 U4.8@2102.37,556.78
  BOTTOM w15: C93.1@2013,384 2012,385 2012,390 v1(2012,446) 2052,446 2076.62,470.62 C82.1@2076.62,502
+3.3VD: C20.2 C41.1 C42.2 C43.2 C50.2 C61.1 C76.1 C86.2 C97.2 R3.2 R14.2 R15.2 R16.2 R68.2 R74.2 R90.2 R91.2 R103.2 R117.2 R124.2 R127.2 R130.2 R133.2 R134.2 R140.2 R155.2 R170.2 R171.2 R172.2 R173.2 R177.1 R194.1 R196.2 R197.2 R200.2 R201.2 R202.2 S2.1 U3.5 U6.7 U6.8 U6.16 U6.26 U6.28 U6.39 U6.47 U6.51 U6.52 U6.69 U6.79 U6.90 U6.101 U6.113 U6.122 U11.1 U11.2 U14.14 | length 17597
  TOP w8: U14.14@1150.24,1260.13 1163.87,1260.13 1179,1245 C97.2@1195.31,1245
  TOP w12: v1(346,1056) 354.7,1047.3 U11.2@381.78,1047.3 ; v1(346,1084.59) 361.41,1084.59 373.11,1072.89 U11.1@381.78,1072.89
  TOP w15: v1(179.5,883) 184.9,888.4 R201.2@184.9,911.21 193.92,911.21 194.38,911.67 208.43,911.67 R200.2@222.7,897.4
  TOP w20: v1(-47,561) -46.31,560.31 R103.2@-18,560.31 ; v1(3.86,1221.14) R74.2@31.96,1221.14 ; R197.2@177.8,996.71 149,967.91 149,896 162,883 v1(179.5,883) ; v1(199,817) 207,809 R90.2@207,790.69 ; v1(216,1572.05) 216.79,1572.84 R68.2@246.04,1572.84 ; R117.2@308.61,475.84 v1(308.61,507) ; C86.2@390.11,1129.1 v1(390.11,1163.89) ; R194.1@544.9,1110.69 571.81,1110.69 v1(584.1,1098.4) ; v1(788,157) 818.36,157 v1(870.18,208.82) 950.36,289 1474,289 1521,336 1521,368.62 R171.2@1496.62,393 R170.2@1496.62,441 v1(1531,441) ; C20.2@986.88,798.85 986.88,827.68 v1(988.2,829) 1001.2,842 1030.31,842 1041.31,831 ; U3.5@1041.31,799.63 1041.31,831 ; R15.2@1114,2118.16 1114,2071.8 v1(1120.4,2065.4) ; v1(1194,1274) 1195.31,1272.69 C97.2@1195.31,1245 ; v1(1236,1345) 1326,1345 1448.72,1222.28 S2.1@1492.9,1222.28 1549.28,1222.28 1566.29,1239.29 v1(1566.29,1243.29) ; R177.1@1246.5,890.03 1187.14,890.03 1143,845.9 1056.21,845.9 1041.31,831 ; v1(1848,1063) 1840.2,1055.2 1840.2,881.51 R3.2@1864.61,857.1 1864.61,847.07 1972.69,739 2111.13,739 2129.71,757.59 2129.71,825.73 2117.13,838.31 R196.2@2098,838.31
  L3 w20: v1(1531,441) 1846,126 2225,126 2309.8,210.8 2309.8,248.58 2547,485.78 v1(2547,576) ; v1(1566.29,1243.29) 1567.12,1243.29 1567.12,1219.03 1585.14,1201.01 1610.62,1201.01 1627.61,1218 1725,1218 1848,1095 v1(1848,1063)
  L3 w32: v1(199,817) 199,795 232,762 703.45,762 786.84,845.39 854.46,845.39 874.07,865 967,865 988.2,843.8 v1(988.2,829)
  L4 w25: v1(216,1572.05) 216,1433.28 v1(3.86,1221.14) -43,1174.28 -43,1011 61,907 155.5,907 v1(179.5,883) 179.5,882.5 v1(135,838) 91,794 33,794 -47,714 v1(-47,561) 254.61,561 v1(308.61,507) 308.61,331.39 382,258 687,258 v1(788,157) ; v1(600,1849.5) 553.8,1803.3 486.6,1803.3 440.5,1849.4 419.6,1849.4 v1(380,1889) 359,1910 359,2179 511.1,2331.1 700.9,2331.1 739.6,2292.4 860.6,2292.4 912.5,2240.5 ; v1(1120.4,2065.4) 1120.4,2094.6 1085.7,2129.3 986.7,2129.3 912.5,2203.5 912.5,2240.5 ; v1(1194,1274) 1236,1316 v1(1236,1345) 1189,1392 1169,1392 1141.87,1419.13 1141.87,1704 1119,1726.87 1119,1864 1146,1891 1222.8,1891 1274,1942.2 1274,2000 1381,2107 1381,2246 1274,2353 998.5,2353 v1(984.6,2339.1) 984.6,2312.6 912.5,2240.5
  L4 w30: v1(584.1,1098.4) 965.6,1098.4 1015,1049 1015,970.24 988.2,943.44 v1(988.2,829)
  BOTTOM w7: 152.35,1397.65 U6.26@208.64,1397.65 253.34,1397.65 ; 166.23,1240.17 U6.16@208.64,1240.17 255.57,1240.17 ; 171.36,1429.14 U6.28@208.64,1429.14 254.24,1429.14 ; U6.7@208.64,1098.43 245.36,1098.43 246.03,1099.1 257.92,1099.1 265.67,1106.85 258.34,1114.18 U6.8@208.64,1114.18 ; 362.18,899.98 U6.122@362.18,944.89 362.18,991.42 ; 362.18,1512.18 U6.39@362.18,1551.19 362.18,1595.98 ; U6.47@488.17,1551.19 488.17,1582.5 499.68,1594.01 ; U6.113@503.92,944.89 503.92,974.56 520.86,991.5 ; U6.51@551.16,1551.19 551.16,1605.41 557.95,1612.2 558.3,1612.55 558.65,1612.2 566.91,1603.94 U6.52@566.91,1551.19 ; 692.89,903.5 U6.101@692.89,944.89 692.89,994.61 ; 767,1098.5 814.87,1098.5 U6.90@814.94,1098.43 ; 767.13,1429.14 U6.69@814.94,1429.14 850.37,1429.14 ; 770.3,1271.66 U6.79@814.94,1271.66
  BOTTOM w8: 850.37,1429.14 864.52,1414.99 893.34,1414.99
  BOTTOM w8.4: 360,1510 362.18,1512.18
  BOTTOM w12: C50.2@146.21,1429.14 171.36,1429.14
  BOTTOM w15: C61.1@146.95,1240.06 147.06,1240.17 147.65,1240.17 166.23,1240.17
  BOTTOM w20: R202.2@45,799.69 45,854 64,873 118,873 135,856 v1(135,838) 156,817 R91.2@156,792.69 ; C50.2@146.21,1429.14 146.14,1429.21 145.95,1429.4 C50.2@145.95,1429.01 145.95,1404.05 152.35,1397.65 ; R140.2@146.55,1199.52 146.55,1239.66 C61.1@146.95,1240.06 ; v1(179.5,883) 222.25,840.25 ; v1(199,817) 222.25,840.25 ; v1(216,1572.05) 216,1670 285.5,1739.5 285.5,1794.5 v1(380,1889) ; 253.34,1397.65 283.85,1397.65 301,1380.5 ; 254.24,1429.14 294.14,1429.14 360,1495 360,1510 ; 255.57,1240.17 289.17,1240.17 301.5,1252.5 v1(390.11,1163.89) ; 265.67,1106.85 323.74,1106.85 v1(346,1084.59) ; 301,1255.5 301,1380.5 ; 362.18,899.98 361.92,899.72 361.92,891 361.92,881.15 ; 362.18,991.42 346,1007.6 v1(346,1056) v1(346,1084.59) ; 362.18,1595.98 C43.2@362.18,1610.16 ; C43.2@362.18,1610.21 C43.2@362.52,1610.16 483.48,1610.21 499.68,1594.01 518.03,1612.36 C42.2@518.22,1612.55 ; 481.14,1612.55 C42.2@518.22,1612.55 ; 520.86,991.5 541.86,1012.5 675,1012.5 692.89,994.61 714,1015.72 714,1074.5 738,1098.5 767,1098.5 ; v1(600,1849.5) 603.5,1846 R16.2@629.31,1846 ; R124.2@637.72,1612.95 598.12,1612.95 558.7,1612.95 558.3,1612.55 C42.2@518.22,1612.55 ; 692.89,903.5 692.78,903.39 R155.2@692.78,880.84 692.78,880.05 634.85,880.05 560.8,806 426,806 405,827 405,863.5 387.35,881.15 364,881.15 361.92,881.15 ; R173.2@759.88,180.84 775.16,180.84 788,168 v1(788,157) v1@788,155.96 ; 767.13,1429.14 349.64,1429.14 301,1380.5 ; 770.3,1271.66 702.96,1271.66 640.8,1209.5 470.5,1209.5 424.89,1163.89 v1(390.11,1163.89) ; v1(870.18,208.82) 874,205 R172.2@874,181.69 ; 893.34,1414.99 901.99,1414.99 913.55,1426.55 R134.2@913.55,1440.6 ; v1(984.6,2339.1) 988.1,2342.6 R14.2@1023.21,2342.6 ; v1(2547,576) 2571,576 2588.5,558.5 R130.2@2588.5,522 2589.5,521 2715.5,521 2716.5,522 2718.5,524 R133.2@2718.5,520 ; 222.25,840.25 223.5,839 304.67,839 346.82,881.15 361.92,881.15 ; v1(346,1084.59) 373.59,1084.59 390.11,1101.11 v1(390.11,1163.89)
AR_1P0_RF1: C19.1 C45.2 C47.2 C98.1 C100.1 L8.2 R46.2 U2.G5 U2.H5 U2.J5 | length 97
  TOP w20: U2.J5@2371.32,1503.49 2373.2,1501.61 U2.H5@2373.2,1477.9 ; v1(2389,1457) 2384.31,1452.31 U2.G5@2371.32,1452.31 2373.2,1454.19 2373.2,1457 U2.H5@2373.2,1477.9 ; v1(2394.83,1485.23) 2380.53,1485.23 U2.H5@2373.2,1477.9
AR_1P0_RF2: C37.1 C57.2 C58.2 C102.1 C103.1 L9.2 R100.2 R137.1 U2.C2 U2.D2 | length 162.3
  TOP w20: U2.C2@2448.09,1349.95 U2.D2@2448.09,1375.54 2480.76,1375.54 2520.35,1335.95 v1(2520.35,1318.1)
  TOP w25: v1(2520.35,1318.1) 2549.1,1318.1 v1(2550.1,1317.1)
AR_1V4_APLL: C13.2 U2.A10 | length 86.4
  TOP w12: 2238.3,1290 2238.3,1293.7 U2.A10@2243.37,1298.77
  TOP w18: C13.2@2234,1232 2238.3,1236.3 2238.3,1290
  TOP w20: C13.2@2226.5,1219.4 2234,1226.9 C13.2@2234,1232
AR_1V4_SYNTH: C14.2 U2.B13 | length 147.9
  TOP w4: 2153.31,1285.31 2153.31,1304.57 ; 2153.52,1304.35 2153.52,1311.28
  TOP w6: 2153.52,1311.28 U2.B13@2166.6,1324.36
  TOP w10: 2141.1,1260 2153.31,1272.2 2153.31,1285.31
  TOP w15: C14.2@2084.45,1220.9 2094.95,1231.4 2112.5,1231.4 2141.1,1260
AR_1V8: C12.2 C17.2 C39.2 C48.2 C51.2 C52.2 C53.2 C90.2 C99.1 C104.1 L6.2 R150.2 U2.B11 U2.B12 U2.D15 U2.F5 U2.K5 U2.R9 | length 1648.5
  TOP w10: U2.R9@2268.96,1657.03 2268.96,1678.96 v1(2279,1689) ; U2.K5@2371.32,1529.08 2400,1557.76 v1(2400,1558)
  TOP w12: v1@2087.46,1375.54 2088,1375.54 U2.D15@2115.42,1375.54 ; 2192.19,1269.8 U2.B12@2192.19,1324.36
  TOP w14: C12.2@2167.2,1228.89 2167.2,1244.81 2192.19,1269.8 ; C90.2@2182,1147.69 2184,1147.69 2194,1157.69 2194,1242.39 2213.8,1262.19 ; 2213.8,1314.1 2213.8,1320.38 U2.B11@2217.78,1324.36
  TOP w15: U2.F5@2371.32,1426.72 2375.28,1426.72 2382,1420 2383.99,1420 2386.46,1417.53 v1(2388,1417.53)
  TOP w18: 2213.8,1262.19 2213.8,1314.1
  TOP w20: v1(2143.17,1217.31) 2155.63,1217.31 C12.2@2167.2,1228.89
  L3 w10: v1@2148,1092.6 2189.24,1051.36 2189.24,980.17 2236.9,932.51 2236.9,911.11 2360.61,787.4 2489.27,787.4 2504.83,771.84 2504.83,696.92 2467.75,659.84 2467.75,523.8 2458.27,514.32 v1(2440.32,514.32)
  BOTTOM w14: v1(2088,1375) 2088,1345.69 C53.2@2091.69,1342 ; R150.2@2404.95,514.32 v1(2440.32,514.32)
  BOTTOM w20: C51.2@2387.91,1389.84 2388,1389.93 v1(2388,1417.53) 2400.53,1417.53 ; v1(2400,1558) 2414.35,1572.35 ; 2414.35,1571.55 2414.35,1572.35 ; C39.2@2420.31,1629 2420.31,1578.31 2414.35,1572.35
  BOTTOM w25: v1@2278.75,1688.75 2294.81,1672.69 2329,1672.69 2343.08,1672.69 2384,1631.77 2384,1631 2386,1629 C39.2@2420.31,1629
  other v1: 2148.05,1093.5 2147.62,1120.27 2147.62,1145.62
AR_1V24: C3.2 C4.2 C6.2 C7.2 C55.1 C89.2 C101.1 C105.1 L5.2 R146.2 U2.G15 U2.H15 U2.N11 U2.P14 U2.P15 U2.R6 | length 2810.6
  TOP w10: C101.1@2029.68,1448 2033.99,1452.31 2056,1452.31 U2.G15@2115.42,1452.31 ; C4.2@2029.69,1484 v1(2057,1484) 2063.1,1477.9 U2.H15@2115.42,1477.9 ; 2097.06,1631.44 U2.P15@2115.42,1631.44 U2.P14@2141.01,1631.44
  TOP w12: U2.R6@2345.73,1657.03 2345.73,1703 2352,1709.27 C3.2@2352,1725.31 2357.31,1720 v1@2373,1720
  TOP w15: v1(2201,1577) 2201,1589.07 U2.N11@2217.78,1605.85
  TOP w20: C89.2@1993.2,1686.3 C6.2@2034.5,1686.3 ; C6.2@2034.5,1685.91 2042.59,1685.91 2097.06,1631.44
  L4 w10: v1(2056,1453) 1994.63,1514.37 1832.51,1514.37 1747.88,1429.74 1747.88,868.36 1623.8,744.27 1623.8,484.97 1623.54,484.71 1685.25,423 2125.14,423 2135.5,433.37 2206.43,433.37 2250.06,477 v1(2481,477)
  BOTTOM w10: v1(2481,477) 2498,460 R146.2@2537,460
  BOTTOM w20: v1@2200.31,1577.69 v1(2201,1577)
  other v1: 1894,1677 1916,1697 1940,1715 1891,1719 2377,1720
AR_3V3: C5.2 C80.1 C84.2 C87.2 L10.2 U2.F15 U2.R10 | length 2795.5
  TOP w10: v1(1932,1445) 1933.69,1443.31 C84.2@1933.69,1419 1956.22,1419 1961.11,1414.11 1983.23,1414.11 1988.11,1419 2066,1419 2073.72,1426.72 U2.F15@2115.42,1426.72 ; v1(2243,1704.83) 2243,1712.26 v1@2243.37,1712.63 ; U2.R10@2243.37,1657.03 2243.37,1704.83 v1@2243.37,1712.63 ; 2248.74,1718 v1@2243.37,1712.63
  TOP w20: C5.2@2211.95,1748.3 2212.14,1748.11 2213.85,1746.4 2241.8,1746.4 2255.3,1759.9 C87.2@2261.8,1759.9
  L4 w30: v1(1932,1445) 2011.46,1365.54 2011.46,1118.62 2106.95,1023.14 2316.75,1023.14 v1(2550,789.89) 2694,933.89 2694,1550.78 2492.58,1752.2 2287.2,1752.2 2243,1708 v1(2243,1704.83)
  BOTTOM w25: L10.2@2547,830.64 2550,827.64 v1(2550,789.89)
AR_ANAMUX: P1.3 U2.C13 | length 2792.8
  TOP w4: v1@2056.9,1213.47 2053.38,1217 v1(2049,1217) 2049,1249.74 2110.82,1311.56 2122.56,1311.56 2128,1317 2128,1330 2134.66,1336.66 2153.31,1336.66 U2.C13@2166.6,1349.95
  L3 w5: P1.3@6.27,1646.15 65,1587.42 65,1495.2 177.4,1382.8 177.4,1356.45 285.85,1248 358,1248 636.25,969.75 760.31,969.75 828.56,1038 1108.06,1038 1201.06,945 1797.78,945 2036.09,1183.32 2036.09,1204.09 v1(2049,1217)
AR_ANATEST1: R46.1 R104.2 U2.P1 | length 4276.8
  TOP w4: R104.2@727.75,512.27 730.02,510 v1(765,510) ; U2.P1@2473.68,1631.44 2485.69,1631.44 2504.26,1650.01 2515.81,1650.01 2564.89,1699.1 2564.89,1726.58 2594.66,1756.35 v1(2594.66,1761.9)
  L3 w4: 1529.65,286.92 1538.97,277.6 v1(1600.06,277.6)
  L3 w5: v1(765,510) 804.19,510 939.19,375 1365.46,375 1396.16,344.3 1472.27,344.3 1529.65,286.92
  L4 w4: v1(1600.06,277.6) 1688.07,277.6 1724.67,241 1853.51,241 1953.05,141.46 2122.98,141.46 2252.64,11.8 2410.65,11.8 2482.43,83.58 2580.03,83.58 2845.54,349.09 2845.54,581.49 2692.23,734.8 2692.23,842 2767.24,917.01 2767.24,1588.08 2594.66,1760.66 v1(2594.66,1761.9)
  BOTTOM w5: v1(2594.66,1761.9) 2621.34,1761.9 R46.1@2629.9,1753.34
